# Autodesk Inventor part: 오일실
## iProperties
IsCustomPart: 0
Company: 한국ATC센터
Created: 2014-08
Part Number: 오일실
Material: 고무
Description: 오일-실
Document SubType Name: Modeling
Standard: KS B 2804
Designer: KYOUNG IL JANG
Standards Organization: KS
Language: ko-KR
Size Designation: S - 17 30 8
Categories: <MemberInstance><Categories><Category DisplayName="샤프트 부품" InternalName="7f7aeb1f-a693-4053-b835-cee3144e0d98" Mnemonic="SHFT"><Category DisplayName="실링" Intern
Density: 0.93 g/cm^3
Mass: 1.6913 g
Surface Area: 28.0102 cm^2
Volume: 1.81861 cm^3
Author: KYOUNG IL JANG
